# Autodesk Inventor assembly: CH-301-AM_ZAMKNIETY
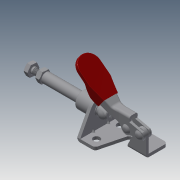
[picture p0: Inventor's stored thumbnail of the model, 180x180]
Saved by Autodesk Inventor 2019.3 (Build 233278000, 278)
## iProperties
Company: Î¢ÈíÖÐ¹ú
Created: 2012-09
Part Number: CH-301-AM_ZAMKNIETY
Material: Ogólny
Description: STEP AP203
Document SubType Name: Assembly
Designer: CADENGINEERING4
Sending System: SolidWorks 2010
Preprocessor: SwSTEP 2.0
Title: CH-301-AM.STEP
Author: Î¢ÈíÓÃ»§
Revision Number: ÈÎºÎ
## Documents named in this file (10)
- D:\Vault_2016\Projekty\STRONA\Push-pull clamp\CH-301-AM\CH-301-AM_ZAMKNIETY.iam
- D:\Vault_2016\Projekty\STRONA\Push-pull clamp\CH-301-AM\CH-SA-042007 SPINDLE SUPPLIED.ipt
- D:\Vault_2016\Projekty\STRONA\Push-pull clamp\CH-301-AM\CH-301-AM-02 CREST STALK.ipt
- D:\Vault_2016\Projekty\STRONA\Push-pull clamp\CH-301-AM\CH-301-AM-05 LEAD SET.ipt
- D:\Vault_2016\Projekty\STRONA\Push-pull clamp\CH-301-AM\CH-301-06.ipt
- D:\Vault_2016\Projekty\STRONA\Push-pull clamp\CH-301-AM\CH-301-AM-03 HANDLE.iam
- D:\Vault_2016\Projekty\STRONA\Push-pull clamp\CH-301-AM\CH-301-07.ipt
- D:\Vault_2016\Projekty\STRONA\Push-pull clamp\CH-301-AM\M4 Nut.ipt
- D:\Vault_2016\Projekty\STRONA\Push-pull clamp\CH-301-AM\CH-301-AM-04 CONNECTING-PLATE.ipt
- D:\Vault_2016\Projekty\STRONA\Push-pull clamp\CH-301-AM\CH-301-AM-01 BASE.ipt
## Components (10 placed, 10 different names)
1. CH-SA-042007 SPINDLE SUPPLIED_1
2. CH-301-AM-02 CREST STALK_2
3. CH-301-AM-05 LEAD SET_3
4. CH-301-06_4
5. CH-301-AM-03 HANDLE_5 [sub-assembly]
6. CH-301-07_6
7. M4 Nut_7
8. CH-301-AM-04 CONNECTING-PLATE_8
9. CH-301-AM-01 BASE_9
10. CH-301-06_10
